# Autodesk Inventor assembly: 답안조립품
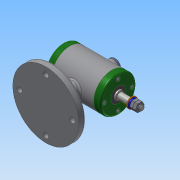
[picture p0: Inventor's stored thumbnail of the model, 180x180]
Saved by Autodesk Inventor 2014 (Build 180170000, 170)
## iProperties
Created: 2018-12
Part Number: 답안조립품
Document SubType Name: Assembly
Designer: net
Author: net
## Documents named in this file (15)
- C:\Users\net\Desktop\481207V1027\답안조립품.iam
- C:\Users\net\Desktop\481207V1027\본체.ipt
- C:\Users\net\Desktop\481207V1027\축.ipt
- C:\Users\net\Desktop\481207V1027\키 3 x 3 x 12.ipt
- C:\Users\net\Desktop\481207V1027\베어링 15 x 32 x 9.ipt
- C:\Users\net\Desktop\481207V1027\V벨트풀리.ipt
- C:\Users\net\Desktop\481207V1027\와셔 8x17.ipt
- C:\Users\net\Desktop\481207V1027\스프링와셔 8.ipt
- C:\Users\net\Desktop\481207V1027\너트 M8.ipt
- 너트 M8.ipt
- C:\Users\net\Desktop\481207V1027\뒤커버.ipt
- C:\Users\net\Desktop\481207V1027\앞커버.ipt
- C:\Users\net\Desktop\481207V1027\오일 실 15 25 7.ipt
- C:\Users\net\Desktop\481207V1027\고무캡.ipt
- C:\Users\net\Desktop\481207V1027\볼트 M4 x 12.ipt
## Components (2 placed, 2 different names)
1. V벨트풀리:1
2. 고무캡:1 — 각도:1, 각도:2
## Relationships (2: Angle 2)
- 각도:1 [Angle]: 고무캡:1
- 각도:2 [Angle]: 고무캡:1
